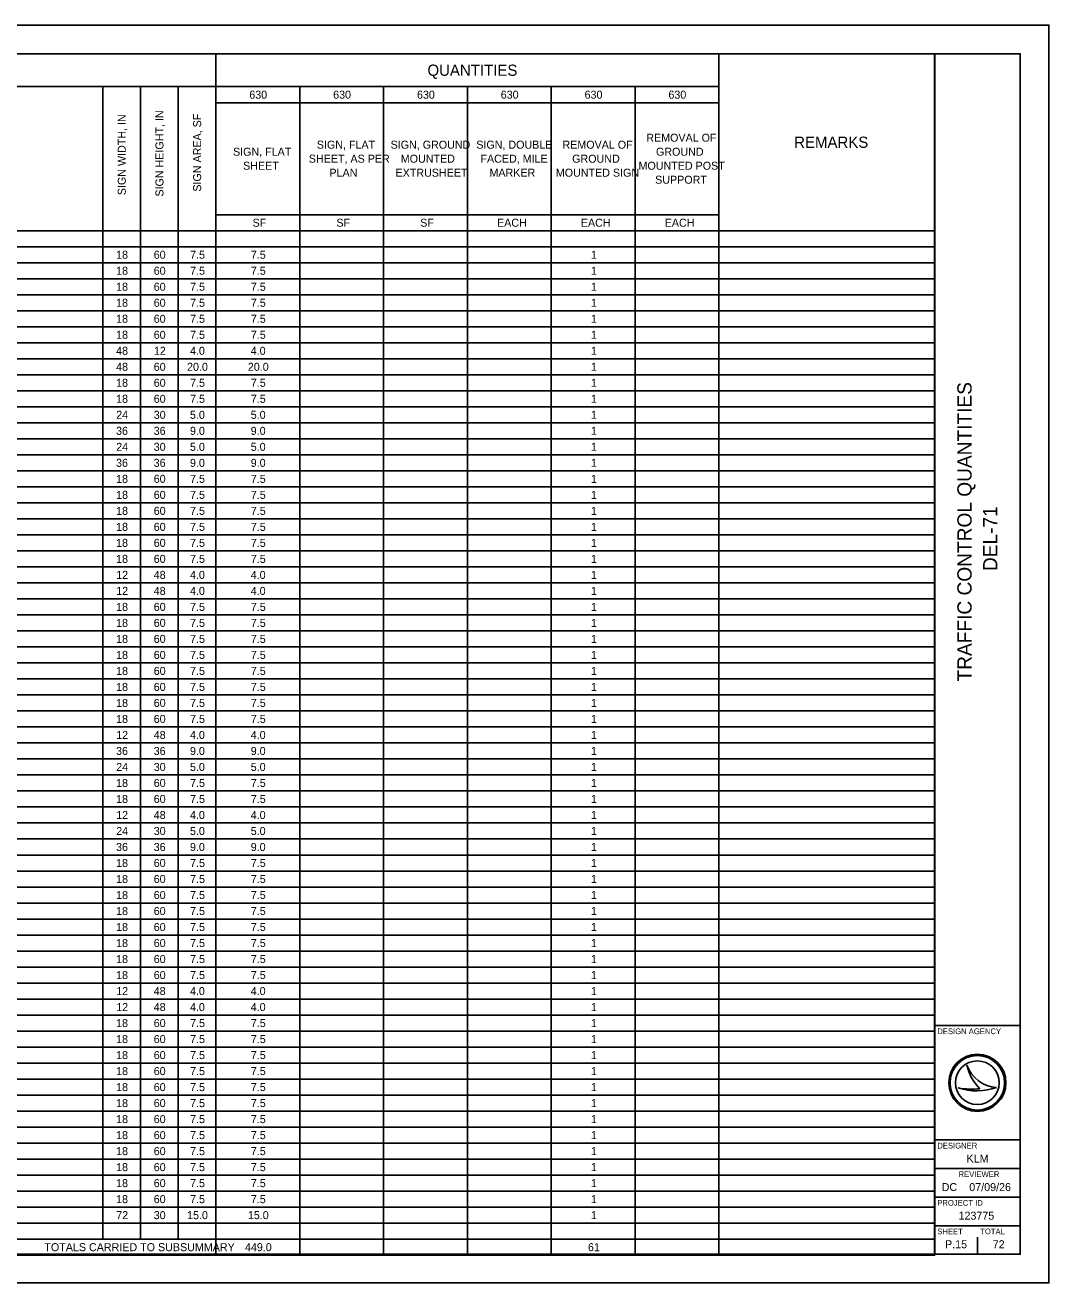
# Model space of a CAD drawing. Extents: x 0 to 34, y 0 to 22.
# Drawn here: x 16.1 to 34, y 0 to 22 of the extents above; entities that cross this region are included whole.
import ezdxf

# ---------------------------------------------------------------- set-up
doc = ezdxf.new("R2010")
doc.units = 0
for name, color, linetype in [('SH_Border', 7, 'Continuous'), ('SH_Cut_Line', 7, 'Continuous'), ('SH_Data', 7, 'Continuous'), ('SH_Text', 7, 'Continuous')]:
    doc.layers.add(name, color=color, linetype=linetype)

msp = doc.modelspace()

# ---------------------------------------------------------------- linework, layer by layer
at = {"layer": 'SH_Border'}
for p, q in [((32, 0.5), (32, 21.5)), ((32, 4.5), (33.5, 4.5)), ((32, 2.5), (33.5, 2.5)), ((32, 2), (33.5, 2)), ((32, 1.5), (33.5, 1.5)), ((32, 1), (33.5, 1))]:
    msp.add_line(p, q, dxfattribs=at)
msp.add_lwpolyline([(1.5, 21.5), (33.5, 21.5), (33.5, 0.5), (1.5, 0.5)], close=True, dxfattribs=at)
at = {"layer": 'SH_Cut_Line'}
msp.add_lwpolyline([(0, 0), (34, 0), (34, 22), (0, 22)], close=True, dxfattribs=at)
at = {"layer": 'SH_Data'}
for p, q in [((1.5, 21.5), (32.004, 21.5)), ((19.436, 21.5), (19.436, 0.484)), ((28.232, 21.5), (28.232, 0.484)), ((32.004, 21.5), (32.004, 0.484)), ((1.5, 20.924), (28.232, 20.924)), ((17.46, 20.924), (17.46, 0.764)), ((18.119, 20.924), (18.119, 0.764)), ((18.778, 20.924), (18.778, 0.764)), ((20.902, 20.924), (20.902, 0.484)), ((22.368, 20.924), (22.368, 0.484)), ((23.834, 20.924), (23.834, 0.484)), ((25.3, 20.924), (25.3, 0.484)), ((26.766, 20.924), (26.766, 0.484)), ((19.436, 20.644), (28.232, 20.644)), ((19.436, 18.684), (28.232, 18.684)), ((1.5, 18.404), (32.004, 18.404)), ((1.5, 18.124), (32.004, 18.124)), ((1.5, 17.844), (32.004, 17.844)), ((1.5, 17.564), (32.004, 17.564)), ((1.5, 17.284), (32.004, 17.284)), ((1.5, 17.004), (32.004, 17.004)), ((1.5, 16.724), (32.004, 16.724)), ((1.5, 16.444), (32.004, 16.444)), ((1.5, 16.164), (32.004, 16.164)), ((1.5, 15.884), (32.004, 15.884)), ((1.5, 15.604), (32.004, 15.604)), ((1.5, 15.324), (32.004, 15.324)), ((1.5, 15.044), (32.004, 15.044)), ((1.5, 14.764), (32.004, 14.764)), ((1.5, 14.484), (32.004, 14.484)), ((1.5, 14.204), (32.004, 14.204)), ((1.5, 13.924), (32.004, 13.924)), ((1.5, 13.644), (32.004, 13.644)), ((1.5, 13.364), (32.004, 13.364)), ((1.5, 13.084), (32.004, 13.084)), ((1.5, 12.804), (32.004, 12.804)), ((1.5, 12.524), (32.004, 12.524)), ((1.5, 12.244), (32.004, 12.244)), ((1.5, 11.964), (32.004, 11.964)), ((1.5, 11.684), (32.004, 11.684)), ((1.5, 11.404), (32.004, 11.404)), ((1.5, 11.124), (32.004, 11.124)), ((1.5, 10.844), (32.004, 10.844)), ((1.5, 10.564), (32.004, 10.564)), ((1.5, 10.284), (32.004, 10.284)), ((1.5, 10.004), (32.004, 10.004)), ((1.5, 9.724), (32.004, 9.724)), ((1.5, 9.444), (32.004, 9.444)), ((1.5, 9.164), (32.004, 9.164)), ((1.5, 8.884), (32.004, 8.884)), ((1.5, 8.604), (32.004, 8.604)), ((1.5, 8.324), (32.004, 8.324)), ((1.5, 8.044), (32.004, 8.044)), ((1.5, 7.764), (32.004, 7.764)), ((1.5, 7.484), (32.004, 7.484)), ((1.5, 7.204), (32.004, 7.204)), ((1.5, 6.924), (32.004, 6.924)), ((1.5, 6.644), (32.004, 6.644)), ((1.5, 6.364), (32.004, 6.364)), ((1.5, 6.084), (32.004, 6.084)), ((1.5, 5.804), (32.004, 5.804)), ((1.5, 5.524), (32.004, 5.524)), ((1.5, 5.244), (32.004, 5.244)), ((1.5, 4.964), (32.004, 4.964)), ((1.5, 4.684), (32.004, 4.684)), ((1.5, 4.404), (32.004, 4.404)), ((1.5, 4.124), (32.004, 4.124)), ((1.5, 3.844), (32.004, 3.844)), ((32.567, 3.81), (32.567, 3.81)), ((1.5, 3.564), (32.004, 3.564)), ((32.417, 3.41), (32.417, 3.41)), ((32.75, 3.5), (32.75, 3.5)), ((33.087, 3.419), (33.087, 3.419)), ((1.5, 3.284), (32.004, 3.284)), ((1.5, 3.004), (32.004, 3.004)), ((1.5, 2.724), (32.004, 2.724)), ((1.5, 2.444), (32.004, 2.444)), ((1.5, 2.164), (32.004, 2.164)), ((1.5, 1.884), (32.004, 1.884)), ((1.5, 1.604), (32.004, 1.604)), ((1.5, 1.324), (32.004, 1.324)), ((1.5, 1.044), (32.004, 1.044)), ((1.5, 0.764), (32.004, 0.764)), ((32.375, 0.675), (32.375, 0.675)), ((32.75, 0.5), (32.75, 0.8)), ((1.5, 0.484), (32.004, 0.484))]:
    msp.add_line(p, q, dxfattribs=at)
for radius in [0.5, 0.477, 0.477, 0.382]:
    msp.add_circle((32.75, 3.5), radius, dxfattribs=at)
for centre, radius, start, end in [((33.116, 3.998), 0.58, 198.9257, 198.9319), ((33.347, 3.97), 0.796, 191.6379, 191.6421), ((33.116, 3.998), 0.58, 198.9319, 267.1657), ((33.347, 3.97), 0.796, 191.6421, 226.0947), ((32.739, 4.37), 1.013, 251.4576, 290.0832), ((32.648, 4.654), 1.266, 259.4964, 259.4995), ((32.739, 4.37), 1.013, 251.4527, 251.4576), ((32.648, 4.654), 1.266, 259.4995, 276.6672)]:
    msp.add_arc(centre, radius, start, end, dxfattribs=at)

# ---------------------------------------------------------------- texts
for s, p in [('TRAFFIC CONTROL QUANTITIES', (32.65, 10.519)), ('DEL-71', (33.1, 12.451))]:
    msp.add_text(s, height=0.25, rotation=90, dxfattribs=at).set_placement(p)
for s, height, p in [('DESIGN AGENCY', 0.1, (32.05, 4.35)), ('DESIGNER', 0.1, (32.05, 2.35)), ('KLM', 0.14, (32.561, 2.105)), ('REVIEWER', 0.1, (32.422, 1.85)), ('DC', 0.14, (32.126, 1.605)), ('07/09/26', 0.14, (32.609, 1.605)), ('PROJECT ID', 0.1, (32.05, 1.35)), ('123775', 0.14, (32.421, 1.105)), ('SHEET', 0.1, (32.05, 0.85)), ('TOTAL', 0.1, (32.8, 0.85)), ('P.15', 0.14, (32.185, 0.605)), ('72', 0.14, (33.019, 0.605))]:
    msp.add_text(s, height=height, dxfattribs=at).set_placement(p)
at = {"layer": 'SH_Text'}
for s, height, p in [('QUANTITIES', 0.196, (23.134, 21.114)), ('630', 0.14, (20.019, 20.714)), ('630', 0.14, (21.485, 20.714)), ('630', 0.14, (22.951, 20.714)), ('630', 0.14, (24.416, 20.714)), ('630', 0.14, (25.882, 20.714)), ('630', 0.14, (27.348, 20.714)), ('REMOVAL OF ', 0.14, (26.961, 19.961)), ('REMARKS', 0.196, (29.547, 19.854)), ('SIGN, FLAT ', 0.14, (19.734, 19.716)), ('SIGN, FLAT ', 0.14, (21.2, 19.839)), ('SIGN, GROUND ', 0.14, (22.49, 19.839)), ('SIGN, DOUBLE ', 0.14, (23.988, 19.839)), ('REMOVAL OF ', 0.14, (25.495, 19.839)), ('GROUND ', 0.14, (27.131, 19.716)), ('SHEET', 0.14, (19.911, 19.471)), ('SHEET, AS PER ', 0.14, (21.06, 19.594)), ('MOUNTED ', 0.14, (22.668, 19.594)), ('FACED, MILE ', 0.14, (24.061, 19.594)), ('GROUND ', 0.14, (25.665, 19.594)), ('MOUNTED POST ', 0.14, (26.825, 19.471)), ('PLAN', 0.14, (21.421, 19.349)), ('EXTRUSHEET', 0.14, (22.576, 19.349)), ('MARKER', 0.14, (24.219, 19.349)), ('MOUNTED SIGN', 0.14, (25.379, 19.349)), ('SUPPORT', 0.14, (27.116, 19.226)), ('SF', 0.14, (20.076, 18.474)), ('SF', 0.14, (21.542, 18.474)), ('SF', 0.14, (23.008, 18.474)), ('EACH', 0.14, (24.351, 18.474)), ('EACH', 0.14, (25.817, 18.474)), ('EACH', 0.14, (27.283, 18.474)), ('18', 0.14, (17.69, 17.914)), ('60', 0.14, (18.348, 17.914)), ('7.5', 0.14, (18.984, 17.914)), ('7.5', 0.14, (20.046, 17.914)), ('1', 0.14, (25.992, 17.914)), ('18', 0.14, (17.69, 17.634)), ('60', 0.14, (18.348, 17.634)), ('7.5', 0.14, (18.984, 17.634)), ('7.5', 0.14, (20.046, 17.634)), ('1', 0.14, (25.992, 17.634)), ('18', 0.14, (17.69, 17.354)), ('60', 0.14, (18.348, 17.354)), ('7.5', 0.14, (18.984, 17.354)), ('7.5', 0.14, (20.046, 17.354)), ('1', 0.14, (25.992, 17.354)), ('18', 0.14, (17.69, 17.074)), ('60', 0.14, (18.348, 17.074)), ('7.5', 0.14, (18.984, 17.074)), ('7.5', 0.14, (20.046, 17.074)), ('1', 0.14, (25.992, 17.074)), ('18', 0.14, (17.69, 16.794)), ('60', 0.14, (18.348, 16.794)), ('7.5', 0.14, (18.984, 16.794)), ('7.5', 0.14, (20.046, 16.794)), ('1', 0.14, (25.992, 16.794)), ('18', 0.14, (17.69, 16.514)), ('60', 0.14, (18.348, 16.514)), ('7.5', 0.14, (18.984, 16.514)), ('7.5', 0.14, (20.046, 16.514)), ('1', 0.14, (25.992, 16.514)), ('48', 0.14, (17.69, 16.234)), ('12', 0.14, (18.351, 16.234)), ('4.0', 0.14, (18.982, 16.234)), ('4.0', 0.14, (20.044, 16.234)), ('1', 0.14, (25.992, 16.234)), ('48', 0.14, (17.69, 15.954)), ('60', 0.14, (18.348, 15.954)), ('20.0', 0.14, (18.931, 15.954)), ('20.0', 0.14, (19.994, 15.954)), ('1', 0.14, (25.992, 15.954)), ('18', 0.14, (17.69, 15.674)), ('60', 0.14, (18.348, 15.674)), ('7.5', 0.14, (18.984, 15.674)), ('7.5', 0.14, (20.046, 15.674)), ('1', 0.14, (25.992, 15.674)), ('18', 0.14, (17.69, 15.394)), ('60', 0.14, (18.348, 15.394)), ('7.5', 0.14, (18.984, 15.394)), ('7.5', 0.14, (20.046, 15.394)), ('1', 0.14, (25.992, 15.394)), ('24', 0.14, (17.692, 15.114)), ('30', 0.14, (18.348, 15.114)), ('5.0', 0.14, (18.982, 15.114)), ('5.0', 0.14, (20.044, 15.114)), ('1', 0.14, (25.992, 15.114)), ('36', 0.14, (17.689, 14.834)), ('36', 0.14, (18.347, 14.834)), ('9.0', 0.14, (18.982, 14.834)), ('9.0', 0.14, (20.044, 14.834)), ('1', 0.14, (25.992, 14.834)), ('24', 0.14, (17.692, 14.554)), ('30', 0.14, (18.348, 14.554)), ('5.0', 0.14, (18.982, 14.554)), ('5.0', 0.14, (20.044, 14.554)), ('1', 0.14, (25.992, 14.554)), ('36', 0.14, (17.689, 14.274)), ('36', 0.14, (18.347, 14.274)), ('9.0', 0.14, (18.982, 14.274)), ('9.0', 0.14, (20.044, 14.274)), ('1', 0.14, (25.992, 14.274)), ('18', 0.14, (17.69, 13.994)), ('60', 0.14, (18.348, 13.994)), ('7.5', 0.14, (18.984, 13.994)), ('7.5', 0.14, (20.046, 13.994)), ('1', 0.14, (25.992, 13.994)), ('18', 0.14, (17.69, 13.714)), ('60', 0.14, (18.348, 13.714)), ('7.5', 0.14, (18.984, 13.714)), ('7.5', 0.14, (20.046, 13.714)), ('1', 0.14, (25.992, 13.714)), ('18', 0.14, (17.69, 13.434)), ('60', 0.14, (18.348, 13.434)), ('7.5', 0.14, (18.984, 13.434)), ('7.5', 0.14, (20.046, 13.434)), ('1', 0.14, (25.992, 13.434)), ('18', 0.14, (17.69, 13.154)), ('60', 0.14, (18.348, 13.154)), ('7.5', 0.14, (18.984, 13.154)), ('7.5', 0.14, (20.046, 13.154)), ('1', 0.14, (25.992, 13.154)), ('18', 0.14, (17.69, 12.874)), ('60', 0.14, (18.348, 12.874)), ('7.5', 0.14, (18.984, 12.874)), ('7.5', 0.14, (20.046, 12.874)), ('1', 0.14, (25.992, 12.874)), ('18', 0.14, (17.69, 12.594)), ('60', 0.14, (18.348, 12.594)), ('7.5', 0.14, (18.984, 12.594)), ('7.5', 0.14, (20.046, 12.594)), ('1', 0.14, (25.992, 12.594)), ('12', 0.14, (17.692, 12.314)), ('48', 0.14, (18.348, 12.314)), ('4.0', 0.14, (18.982, 12.314)), ('4.0', 0.14, (20.044, 12.314)), ('1', 0.14, (25.992, 12.314)), ('12', 0.14, (17.692, 12.034)), ('48', 0.14, (18.348, 12.034)), ('4.0', 0.14, (18.982, 12.034)), ('4.0', 0.14, (20.044, 12.034)), ('1', 0.14, (25.992, 12.034)), ('18', 0.14, (17.69, 11.754)), ('60', 0.14, (18.348, 11.754)), ('7.5', 0.14, (18.984, 11.754)), ('7.5', 0.14, (20.046, 11.754)), ('1', 0.14, (25.992, 11.754)), ('18', 0.14, (17.69, 11.474)), ('60', 0.14, (18.348, 11.474)), ('7.5', 0.14, (18.984, 11.474)), ('7.5', 0.14, (20.046, 11.474)), ('1', 0.14, (25.992, 11.474)), ('18', 0.14, (17.69, 11.194)), ('60', 0.14, (18.348, 11.194)), ('7.5', 0.14, (18.984, 11.194)), ('7.5', 0.14, (20.046, 11.194)), ('1', 0.14, (25.992, 11.194)), ('18', 0.14, (17.69, 10.914)), ('60', 0.14, (18.348, 10.914)), ('7.5', 0.14, (18.984, 10.914)), ('7.5', 0.14, (20.046, 10.914)), ('1', 0.14, (25.992, 10.914)), ('18', 0.14, (17.69, 10.634)), ('60', 0.14, (18.348, 10.634)), ('7.5', 0.14, (18.984, 10.634)), ('7.5', 0.14, (20.046, 10.634)), ('1', 0.14, (25.992, 10.634)), ('18', 0.14, (17.69, 10.354)), ('60', 0.14, (18.348, 10.354)), ('7.5', 0.14, (18.984, 10.354)), ('7.5', 0.14, (20.046, 10.354)), ('1', 0.14, (25.992, 10.354)), ('18', 0.14, (17.69, 10.074)), ('60', 0.14, (18.348, 10.074)), ('7.5', 0.14, (18.984, 10.074)), ('7.5', 0.14, (20.046, 10.074)), ('1', 0.14, (25.992, 10.074)), ('18', 0.14, (17.69, 9.794)), ('60', 0.14, (18.348, 9.794)), ('7.5', 0.14, (18.984, 9.794)), ('7.5', 0.14, (20.046, 9.794)), ('1', 0.14, (25.992, 9.794)), ('12', 0.14, (17.692, 9.514)), ('48', 0.14, (18.348, 9.514)), ('4.0', 0.14, (18.982, 9.514)), ('4.0', 0.14, (20.044, 9.514)), ('1', 0.14, (25.992, 9.514)), ('36', 0.14, (17.689, 9.234)), ('36', 0.14, (18.347, 9.234)), ('9.0', 0.14, (18.982, 9.234)), ('9.0', 0.14, (20.044, 9.234)), ('1', 0.14, (25.992, 9.234)), ('24', 0.14, (17.692, 8.954)), ('30', 0.14, (18.348, 8.954)), ('5.0', 0.14, (18.982, 8.954)), ('5.0', 0.14, (20.044, 8.954)), ('1', 0.14, (25.992, 8.954)), ('18', 0.14, (17.69, 8.674)), ('60', 0.14, (18.348, 8.674)), ('7.5', 0.14, (18.984, 8.674)), ('7.5', 0.14, (20.046, 8.674)), ('1', 0.14, (25.992, 8.674)), ('18', 0.14, (17.69, 8.394)), ('60', 0.14, (18.348, 8.394)), ('7.5', 0.14, (18.984, 8.394)), ('7.5', 0.14, (20.046, 8.394)), ('1', 0.14, (25.992, 8.394)), ('12', 0.14, (17.692, 8.114)), ('48', 0.14, (18.348, 8.114)), ('4.0', 0.14, (18.982, 8.114)), ('4.0', 0.14, (20.044, 8.114)), ('1', 0.14, (25.992, 8.114)), ('24', 0.14, (17.692, 7.834)), ('30', 0.14, (18.348, 7.834)), ('5.0', 0.14, (18.982, 7.834)), ('5.0', 0.14, (20.044, 7.834)), ('1', 0.14, (25.992, 7.834)), ('36', 0.14, (17.689, 7.554)), ('36', 0.14, (18.347, 7.554)), ('9.0', 0.14, (18.982, 7.554)), ('9.0', 0.14, (20.044, 7.554)), ('1', 0.14, (25.992, 7.554)), ('18', 0.14, (17.69, 7.274)), ('60', 0.14, (18.348, 7.274)), ('7.5', 0.14, (18.984, 7.274)), ('7.5', 0.14, (20.046, 7.274)), ('1', 0.14, (25.992, 7.274)), ('18', 0.14, (17.69, 6.994)), ('60', 0.14, (18.348, 6.994)), ('7.5', 0.14, (18.984, 6.994)), ('7.5', 0.14, (20.046, 6.994)), ('1', 0.14, (25.992, 6.994)), ('18', 0.14, (17.69, 6.714)), ('60', 0.14, (18.348, 6.714)), ('7.5', 0.14, (18.984, 6.714)), ('7.5', 0.14, (20.046, 6.714)), ('1', 0.14, (25.992, 6.714)), ('18', 0.14, (17.69, 6.434)), ('60', 0.14, (18.348, 6.434)), ('7.5', 0.14, (18.984, 6.434)), ('7.5', 0.14, (20.046, 6.434)), ('1', 0.14, (25.992, 6.434)), ('18', 0.14, (17.69, 6.154)), ('60', 0.14, (18.348, 6.154)), ('7.5', 0.14, (18.984, 6.154)), ('7.5', 0.14, (20.046, 6.154)), ('1', 0.14, (25.992, 6.154)), ('18', 0.14, (17.69, 5.874)), ('60', 0.14, (18.348, 5.874)), ('7.5', 0.14, (18.984, 5.874)), ('7.5', 0.14, (20.046, 5.874)), ('1', 0.14, (25.992, 5.874)), ('18', 0.14, (17.69, 5.594)), ('60', 0.14, (18.348, 5.594)), ('7.5', 0.14, (18.984, 5.594)), ('7.5', 0.14, (20.046, 5.594)), ('1', 0.14, (25.992, 5.594)), ('18', 0.14, (17.69, 5.314)), ('60', 0.14, (18.348, 5.314)), ('7.5', 0.14, (18.984, 5.314)), ('7.5', 0.14, (20.046, 5.314)), ('1', 0.14, (25.992, 5.314)), ('12', 0.14, (17.692, 5.034)), ('48', 0.14, (18.348, 5.034)), ('4.0', 0.14, (18.982, 5.034)), ('4.0', 0.14, (20.044, 5.034)), ('1', 0.14, (25.992, 5.034)), ('12', 0.14, (17.692, 4.754)), ('48', 0.14, (18.348, 4.754)), ('4.0', 0.14, (18.982, 4.754)), ('4.0', 0.14, (20.044, 4.754)), ('1', 0.14, (25.992, 4.754)), ('18', 0.14, (17.69, 4.474)), ('60', 0.14, (18.348, 4.474)), ('7.5', 0.14, (18.984, 4.474)), ('7.5', 0.14, (20.046, 4.474)), ('1', 0.14, (25.992, 4.474)), ('18', 0.14, (17.69, 4.194)), ('60', 0.14, (18.348, 4.194)), ('7.5', 0.14, (18.984, 4.194)), ('7.5', 0.14, (20.046, 4.194)), ('1', 0.14, (25.992, 4.194)), ('18', 0.14, (17.69, 3.914)), ('60', 0.14, (18.348, 3.914)), ('7.5', 0.14, (18.984, 3.914)), ('7.5', 0.14, (20.046, 3.914)), ('1', 0.14, (25.992, 3.914)), ('18', 0.14, (17.69, 3.634)), ('60', 0.14, (18.348, 3.634)), ('7.5', 0.14, (18.984, 3.634)), ('7.5', 0.14, (20.046, 3.634)), ('1', 0.14, (25.992, 3.634)), ('18', 0.14, (17.69, 3.354)), ('60', 0.14, (18.348, 3.354)), ('7.5', 0.14, (18.984, 3.354)), ('7.5', 0.14, (20.046, 3.354)), ('1', 0.14, (25.992, 3.354)), ('18', 0.14, (17.69, 3.074)), ('60', 0.14, (18.348, 3.074)), ('7.5', 0.14, (18.984, 3.074)), ('7.5', 0.14, (20.046, 3.074)), ('1', 0.14, (25.992, 3.074)), ('18', 0.14, (17.69, 2.794)), ('60', 0.14, (18.348, 2.794)), ('7.5', 0.14, (18.984, 2.794)), ('7.5', 0.14, (20.046, 2.794)), ('1', 0.14, (25.992, 2.794)), ('18', 0.14, (17.69, 2.514)), ('60', 0.14, (18.348, 2.514)), ('7.5', 0.14, (18.984, 2.514)), ('7.5', 0.14, (20.046, 2.514)), ('1', 0.14, (25.992, 2.514)), ('18', 0.14, (17.69, 2.234)), ('60', 0.14, (18.348, 2.234)), ('7.5', 0.14, (18.984, 2.234)), ('7.5', 0.14, (20.046, 2.234)), ('1', 0.14, (25.992, 2.234)), ('18', 0.14, (17.69, 1.954)), ('60', 0.14, (18.348, 1.954)), ('7.5', 0.14, (18.984, 1.954)), ('7.5', 0.14, (20.046, 1.954)), ('1', 0.14, (25.992, 1.954)), ('18', 0.14, (17.69, 1.674)), ('60', 0.14, (18.348, 1.674)), ('7.5', 0.14, (18.984, 1.674)), ('7.5', 0.14, (20.046, 1.674)), ('1', 0.14, (25.992, 1.674)), ('18', 0.14, (17.69, 1.394)), ('60', 0.14, (18.348, 1.394)), ('7.5', 0.14, (18.984, 1.394)), ('7.5', 0.14, (20.046, 1.394)), ('1', 0.14, (25.992, 1.394)), ('72', 0.14, (17.692, 1.114)), ('30', 0.14, (18.348, 1.114)), ('15.0', 0.14, (18.931, 1.114)), ('15.0', 0.14, (19.994, 1.114)), ('1', 0.14, (25.992, 1.114)), ('TOTALS CARRIED TO SUBSUMMARY', 0.14, (16.436, 0.554)), ('449.0', 0.14, (19.943, 0.554)), ('61', 0.14, (25.941, 0.554))]:
    msp.add_text(s, height=height, dxfattribs=at).set_placement(p)
for s, p in [('SIGN HEIGHT, IN', (18.518, 19.001)), ('SIGN WIDTH, IN', (17.859, 19.026)), ('SIGN AREA, SF', (19.177, 19.088))]:
    msp.add_text(s, height=0.14, rotation=90, dxfattribs=at).set_placement(p)

doc.saveas('drawing.dxf')
